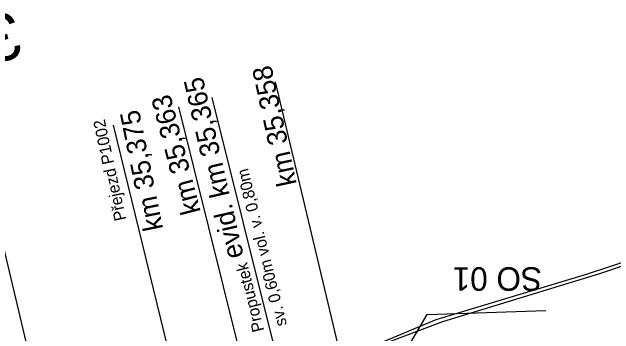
# Model space of a CAD drawing. Extents: x -806456 to -805395, y -1150847 to -1150506.
# Drawn here: x -806195.1 to -806118.3, y -1150682.7 to -1150641.7 of the extents above; entities that cross this region are included whole.
import ezdxf

# ---------------------------------------------------------------- set-up
doc = ezdxf.new("R2010")
doc.units = 0
for name, color, linetype in [('0381KM032-037P - Vrstva 17', 7, 'Continuous'), ('0381KM032-037P - Vrstva 19', 7, 'Continuous'), ('0381KM032-037P - Vrstva 3', 7, 'Continuous'), ('0381KM032-037P - Vrstva 4', 7, 'Continuous'), ('0381KM032-037P - Vrstva 51', 7, 'Continuous'), ('0381KM032-037P - Vrstva 7', 7, 'Continuous'), ('Default', 7, 'Continuous')]:
    doc.layers.add(name, color=color, linetype=linetype)

msp = doc.modelspace()

# ---------------------------------------------------------------- linework, layer by layer
at = {"layer": '0381KM032-037P - Vrstva 17'}
msp.add_lwpolyline([(-806169.284, -1150696.914), (-806165.684, -1150693.969), (-806155.413, -1150686.939), (-806141.029, -1150680.901), (-806121.846, -1150675.136), (-806106.33, -1150670.053), (-806095.392, -1150665.453)], dxfattribs=at)
at = {"layer": '0381KM032-037P - Vrstva 19'}
msp.add_line((-806157.446, -1150701.329), (-806169.593, -1150652.631), dxfattribs=at)
at = {"layer": '0381KM032-037P - Vrstva 3'}
msp.add_line((-806186.46, -1150712.29), (-806198.557, -1150661.727), dxfattribs=at)
msp.add_lwpolyline([(-806158.28, -1150704.94), (-806161.571, -1150691.159), (-806164.309, -1150692.072), (-806173.835, -1150653.806)], dxfattribs=at)
at = {"layer": '0381KM032-037P - Vrstva 4'}
msp.add_line((-806169.501, -1150707.868), (-806182.162, -1150656.159), dxfattribs=at)
at = {"layer": '0381KM032-037P - Vrstva 51'}
for points in [[(-806140.159, -1150681.153), (-806120.154, -1150675.046), (-806107.443, -1150670.762), (-806090.701, -1150663.496), (-806064.751, -1150649.453)], [(-806195.218, -1150723.443), (-806183.651, -1150718.077), (-806179.484, -1150714.678), (-806176.794, -1150711.837), (-806173.358, -1150707), (-806168.375, -1150700.145), (-806163.106, -1150693.208), (-806157.224, -1150688.717), (-806150.874, -1150685.207), (-806140.159, -1150681.153)]]:
    msp.add_lwpolyline(points, dxfattribs=at)
at = {"layer": '0381KM032-037P - Vrstva 7'}
msp.add_lwpolyline([(-806154.215, -1150699.444), (-806156.181, -1150690.115), (-806152.272, -1150689.343), (-806161.508, -1150650.617)], dxfattribs=at)
at = {"layer": 'Default'}
msp.add_lwpolyline([(-806156.561, -1150704.831), (-806142.158, -1150680.251), (-806127.056, -1150679.769)], dxfattribs=at)

# ---------------------------------------------------------------- texts
at = {"layer": '0381KM032-037P - Vrstva 19'}
for s, height, rotation, p in [('evid. km 35,365', 2.5, 102.91118, (-806165.536, -1150672.85)), ('sv. 0,60m vol. v. 0,80m', 1.5, 104.00598, (-806160.035, -1150681.572)), ('Propustek', 1.5, 104.00598, (-806162.946, -1150682.298))]:
    msp.add_text(s, height=height, rotation=rotation, dxfattribs=at).set_placement(p)
at = {"layer": '0381KM032-037P - Vrstva 3'}
msp.add_text('km 35,363', height=2.5, rotation=104.63828, dxfattribs=at).set_placement((-806171.02, -1150667.178))
at = {"layer": '0381KM032-037P - Vrstva 4'}
for s, height, rotation, p in [('km 35,375', 2.5, 101.49293, (-806175.824, -1150669.353)), ('Přejezd P1002', 1.5, 102.15535, (-806180.533, -1150668.168))]:
    msp.add_text(s, height=height, rotation=rotation, dxfattribs=at).set_placement(p)
at = {"layer": '0381KM032-037P - Vrstva 7'}
for s, height, rotation, p in [('35,4', 6, 194.58811, (-806194.84, -1150641.468)), ('km 35,358', 2.5, 102.15943, (-806158.786, -1150663.647))]:
    msp.add_text(s, height=height, rotation=rotation, dxfattribs=at).set_placement(p)
at = {"layer": 'Default'}
msp.add_text('SO 01', height=3, rotation=180, dxfattribs=at).set_placement((-806127.543, -1150674.249))

doc.saveas('drawing.dxf')
